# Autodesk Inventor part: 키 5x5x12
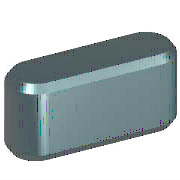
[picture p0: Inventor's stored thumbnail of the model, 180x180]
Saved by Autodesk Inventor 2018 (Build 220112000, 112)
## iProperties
IsCustomPart: 1
Created: 2012-02
Part Number: 키 5x5x12
Material: 강철, 연강
Description: 키 및 해당 키홈
Document SubType Name: Modeling
Standard: KS B 1311
Designer: mduedu
Standards Organization: KS
Language: ko-KR
Size Designation: 5 x 5 x 12
Categories: <MemberInstance><Categories><Category DisplayName="샤프트 부품" InternalName="7f7aeb1f-a693-4053-b835-cee3144e0d98" Mnemonic="SHFT"><Category DisplayName="키" Interna
Density: 1 g/cm^3
Appearance: 노란색
Author: mduedu
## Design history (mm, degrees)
workplane "Work Plane1"
workplane "Work Plane2"
sketch "스케치1"
  geometry: L1 (2.5, 2.5)-(9.5, 2.5); L2 (9.5, -2.5)-(2.5, -2.5); L3 (0, 9.4)-(0, -7.4) reference; L4 (-5, 0)-(30, 0) reference; L5 (12, 0)-(12, 7); A1 r 2.5 centre (2.5, 0) between (2.5, 2.5) and (2.5, -2.5); A2 r 2.5 centre (9.5, 0) between (9.5, -2.5) and (9.5, 2.5)
  constraints: 6 end point, 5 point on circle, 4 tangent, 3 point on line, 2 centre point, 1 horizontal, 1 parallel, 1 perpendicular
  dimensions: "d0" = 2.5 radius of A1 (= 0.5 x PB); "d13" = 2.5 radius of A2 (= 0.5 x PB); "d14" = 12 distance between parallel lines of L5 L3 (= NLG)
extrude "본체1" new body sketch "스케치1" taper "d3" = 0 deg; stored distance "d4" = 10
workplane "Work Plane3"
body "Solid1"
chamfer "모따기1" distance "d8" = 0.4 (= PHH); stored, may be unused: second distance "d9" = 0.4 (= PHH), angle "d15" = 45 deg
other parameters: "d1" = -3 (= -PNT), "d2" = 2 (= PH - PNT), "NLG" = 12 [user parameter; used in 3 equation terms], "PB" = 5 [user parameter; used in 2 equation terms], "PNT" = 3 [user parameter; used in 2 equation terms], "PH" = 5 [user parameter; used in 1 equation term], "PHH" = 0.4 [user parameter; used in 2 equation terms], "d10" = 0, "d16" = 0, "d17" = 0, "d18" = 0, "WDMIN" = 12 [user parameter], "PLB2" = 12 (= NLG) [user parameter], "WDMAX" = 17 [user parameter], "PLB1" = 12 (= NLG) [user parameter], "RR" = 0.16 [user parameter], "PUEB" = 2.3 [user parameter]
